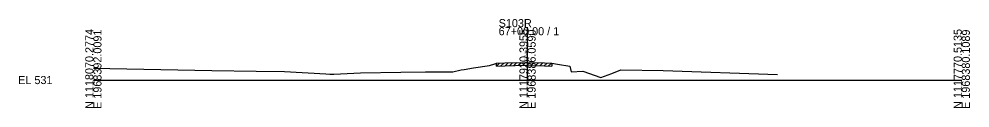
# Model space of a CAD drawing. Extents: x 974 to 1303, y 990 to 10019.
# Drawn here: x 974.3 to 1302.8, y 8990.3 to 9021.2 of the extents above; entities that cross this region are included whole.
import ezdxf

# ---------------------------------------------------------------- set-up
doc = ezdxf.new("R2010")
doc.units = 0
for name, color, linetype in [('Level 10', 7, 'Continuous'), ('Level 60', 7, 'Continuous'), ('Level 61', 7, 'Continuous'), ('Level 63', 7, 'Continuous')]:
    doc.layers.add(name, color=color, linetype=linetype)

msp = doc.modelspace()

# ---------------------------------------------------------------- linework, layer by layer
at = {"layer": 'Level 60'}
for p, q in [((1136.89, 9005.02), (1138.7, 9005.58)), ((1138.7, 9005.58), (1139.28, 9005.84)), ((1139.28, 9005.84), (1142.18, 9005.91)), ((1142.18, 9005.91), (1149.41, 9006.1)), ((1149.41, 9006.1), (1150, 9006.09)), ((1150, 9006.09), (1155.85, 9005.91)), ((1155.85, 9005.91), (1158.38, 9005.84)), ((1158.38, 9005.84), (1160.34, 9005.51)), ((1160.34, 9005.51), (1164.59, 9004.75)), ((1000, 9004.07), (1001.23, 9004.07)), ((1001.23, 9004.07), (1001.67, 9004.07)), ((1001.67, 9004.07), (1005.69, 9003.99)), ((1005.69, 9003.99), (1040.91, 9003.33)), ((1040.91, 9003.33), (1056.29, 9003.05)), ((1056.29, 9003.05), (1066.05, 9002.92)), ((1066.05, 9002.92), (1080.29, 9002.1)), ((1080.29, 9002.1), (1081.74, 9002.02)), ((1081.74, 9002.02), (1083.09, 9002.08)), ((1083.09, 9002.08), (1092.23, 9002.51)), ((1092.23, 9002.51), (1106.24, 9002.69)), ((1106.24, 9002.69), (1114.69, 9002.8)), ((1114.69, 9002.8), (1118.63, 9002.86)), ((1118.63, 9002.86), (1124.14, 9002.79)), ((1124.14, 9002.79), (1127.04, 9003.59)), ((1127.04, 9003.59), (1128.09, 9003.65)), ((1128.09, 9003.65), (1131.36, 9004.18)), ((1131.36, 9004.18), (1136.89, 9005.02)), ((1164.59, 9004.75), (1165.08, 9002.87)), ((1165.08, 9002.87), (1169.1, 9003.12)), ((1169.1, 9003.12), (1175.26, 9000.88)), ((1175.26, 9000.88), (1179.09, 9002.24)), ((1179.09, 9002.24), (1182.2, 9003.52)), ((1182.2, 9003.52), (1196.86, 9003.27)), ((1196.86, 9003.27), (1236.35, 9001.92))]:
    msp.add_line(p, q, dxfattribs=at)
at = {"layer": 'Level 61'}
for p, q in [((1139.28, 9004.84), (1140.31, 9005.86)), ((1139.28, 9004.84), (1139.28, 9005.84)), ((1140.78, 9004.87), (1141.81, 9005.9)), ((1142.18, 9004.91), (1149.41, 9005.1)), ((1142.28, 9004.91), (1143.31, 9005.94)), ((1143.78, 9004.95), (1144.81, 9005.98)), ((1145.28, 9004.99), (1146.31, 9006.02)), ((1146.78, 9005.03), (1147.81, 9006.06)), ((1148.28, 9005.07), (1149.31, 9006.1)), ((1149.41, 9005.1), (1150, 9005.09)), ((1149.78, 9005.09), (1150.76, 9006.06)), ((1150, 9005.09), (1155.85, 9004.91)), ((1151.28, 9005.05), (1152.26, 9006.02)), ((1152.78, 9005), (1153.76, 9005.97)), ((1154.28, 9004.96), (1155.26, 9005.93)), ((1155.78, 9004.91), (1156.76, 9005.88)), ((1157.28, 9004.87), (1158.26, 9005.84)), ((1158.38, 9005.84), (1158.38, 9004.84)), ((1139.28, 9004.84), (1142.18, 9004.91)), ((1155.85, 9004.91), (1158.38, 9004.84)), ((1158.38, 9004.84), (1158.38, 9004.84))]:
    msp.add_line(p, q, dxfattribs=at)
at = {"layer": 'Level 63'}
for p, q in [((1150, 9000), (1150, 9018.31)), ((1000, 9000), (1150, 9000)), ((1150, 9000), (1300, 9000))]:
    msp.add_line(p, q, dxfattribs=at)

# ---------------------------------------------------------------- texts
at = {"layer": 'Level 10'}
msp.add_text('537.09', height=0.9, rotation=90, dxfattribs=at).set_placement((1149.95, 9006.59))
at = {"layer": 'Level 63'}
for s, p in [('S103R', (1140, 9018.31)), ('67+00.00 / 1', (1140, 9015.51)), ('EL 531', (974, 8998.6))]:
    msp.add_text(s, height=2.8, dxfattribs=at).set_placement(p)
for s, p in [('N 1118070.2774', (1000, 8990)), ('E 1968392.0091', (1002.8, 8990)), ('N 1117920.3955', (1150, 8990)), ('E 1968386.0590', (1152.8, 8990)), ('N 1117770.5135', (1300, 8990)), ('E 1968380.1089', (1302.8, 8990))]:
    msp.add_text(s, height=2.8, rotation=90, dxfattribs=at).set_placement(p)

doc.saveas('drawing.dxf')
